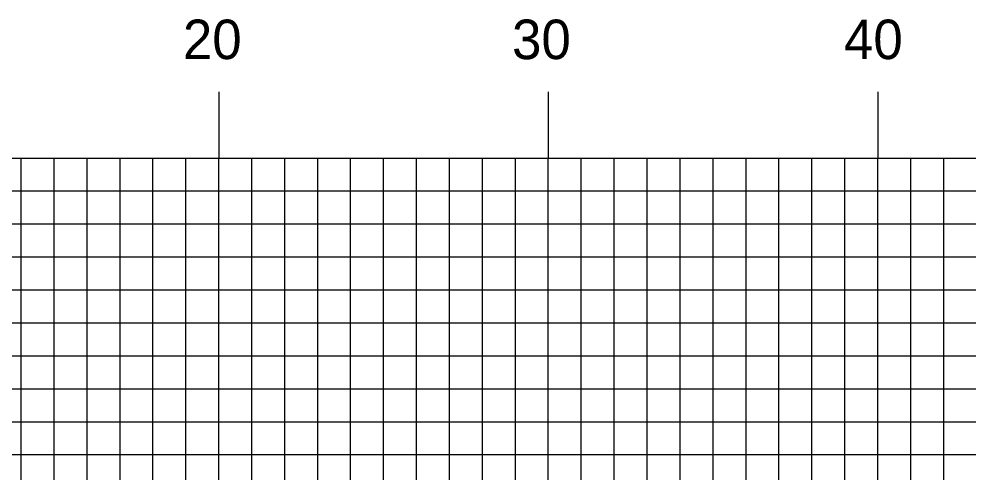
# Model space of a CAD drawing. Extents: x 843356 to 843699, y 363538 to 363758.
# Drawn here: x 843535.36 to 843564.19, y 363616.16 to 363629.94 of the extents above; entities that cross this region are included whole.
import ezdxf

# ---------------------------------------------------------------- set-up
doc = ezdxf.new("R2010")
doc.units = 0
for name, color, linetype in [('H_V ANNOTATION', 7, 'Continuous'), ('MAJOR', 7, 'Continuous'), ('MINOR', 7, 'Continuous')]:
    doc.layers.add(name, color=color, linetype=linetype)

msp = doc.modelspace()

# ---------------------------------------------------------------- linework, layer by layer
at = {"layer": 'MAJOR'}
for p, q in [((843541.424, 363627.725), (843541.424, 363625.721)), ((843551.424, 363627.725), (843551.424, 363625.721)), ((843561.424, 363627.725), (843561.424, 363625.721)), ((843381.424, 363625.721), (843661.424, 363625.721)), ((843381.424, 363625.721), (843661.424, 363625.721)), ((843541.424, 363600.721), (843541.424, 363625.721)), ((843551.424, 363600.721), (843551.424, 363625.721)), ((843561.424, 363600.721), (843561.424, 363625.721)), ((843381.424, 363620.721), (843661.424, 363620.721))]:
    msp.add_line(p, q, dxfattribs=at)
at = {"layer": 'MINOR'}
for p, q in [((843535.424, 363600.721), (843535.424, 363625.721)), ((843536.424, 363600.721), (843536.424, 363625.721)), ((843537.424, 363600.721), (843537.424, 363625.721)), ((843538.424, 363600.721), (843538.424, 363625.721)), ((843539.424, 363600.721), (843539.424, 363625.721)), ((843540.424, 363600.721), (843540.424, 363625.721)), ((843542.424, 363600.721), (843542.424, 363625.721)), ((843543.424, 363600.721), (843543.424, 363625.721)), ((843544.424, 363600.721), (843544.424, 363625.721)), ((843545.424, 363600.721), (843545.424, 363625.721)), ((843546.424, 363600.721), (843546.424, 363625.721)), ((843547.424, 363600.721), (843547.424, 363625.721)), ((843548.424, 363600.721), (843548.424, 363625.721)), ((843549.424, 363600.721), (843549.424, 363625.721)), ((843550.424, 363600.721), (843550.424, 363625.721)), ((843552.424, 363600.721), (843552.424, 363625.721)), ((843553.424, 363600.721), (843553.424, 363625.721)), ((843554.424, 363600.721), (843554.424, 363625.721)), ((843555.424, 363600.721), (843555.424, 363625.721)), ((843556.424, 363600.721), (843556.424, 363625.721)), ((843557.424, 363600.721), (843557.424, 363625.721)), ((843558.424, 363600.721), (843558.424, 363625.721)), ((843559.424, 363600.721), (843559.424, 363625.721)), ((843560.424, 363600.721), (843560.424, 363625.721)), ((843562.424, 363600.721), (843562.424, 363625.721)), ((843563.424, 363600.721), (843563.424, 363625.721)), ((843381.424, 363624.721), (843661.424, 363624.721)), ((843381.424, 363623.721), (843661.424, 363623.721)), ((843381.424, 363622.721), (843661.424, 363622.721)), ((843381.424, 363621.721), (843661.424, 363621.721)), ((843381.424, 363619.721), (843661.424, 363619.721)), ((843381.424, 363618.721), (843661.424, 363618.721)), ((843381.424, 363617.721), (843661.424, 363617.721)), ((843381.424, 363616.721), (843661.424, 363616.721))]:
    msp.add_line(p, q, dxfattribs=at)

# ---------------------------------------------------------------- texts
at = {"layer": 'H_V ANNOTATION'}
for s, p in [('20', (843540.332, 363628.721)), ('30', (843550.322, 363628.721)), ('40', (843560.397, 363628.721))]:
    msp.add_text(s, height=1.2, dxfattribs=at).set_placement(p)

doc.saveas('drawing.dxf')
